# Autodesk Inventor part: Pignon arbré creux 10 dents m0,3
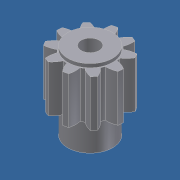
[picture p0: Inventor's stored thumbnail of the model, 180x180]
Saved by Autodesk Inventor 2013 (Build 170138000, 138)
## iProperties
Created: 2011-10
Part Number: Pignon arbré creux 10 dents m0,3
Document SubType Name: Modeling
Designer: Laur
Density: 1 g/cm^3
Material: Générique
Author: Laur
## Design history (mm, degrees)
derived "Pignon arbré creux 10 dents m0,3.iam"
node "Solide1"
node "Corps solides"
node "Corps surfaciques"
node "arbre creux inter.ipt:1"
node "Engrenages cylindriques:1::Engrenage cylindrique1:1"
